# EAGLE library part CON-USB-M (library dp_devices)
USB Male connector
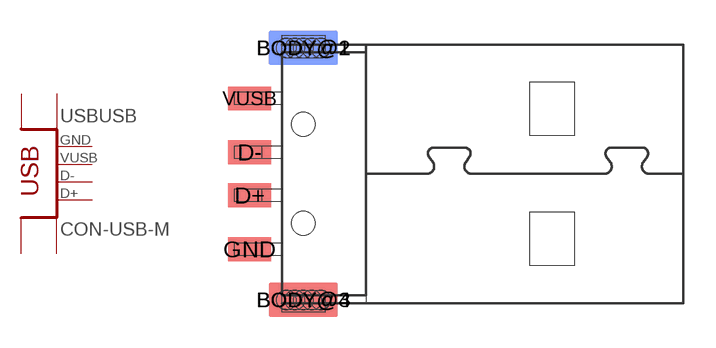
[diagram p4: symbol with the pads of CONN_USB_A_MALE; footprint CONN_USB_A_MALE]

Designator prefix USB; gates USB=CONN_USB_4P BODY=USB_BODY_PINS2

## CON-USB-M-A  [CONN_USB_A_MALE]
BODY@1  BODY:BODY  hiz
BODY@2  BODY:BODY  hiz
BODY@3  BODY:BODY  hiz
BODY@4  BODY:BODY  hiz
D+  USB:D+
D-  USB:D-
GND  USB:GND
VUSB  USB:VUSB

## Footprint CONN_USB_A_MALE (pad centres in mm)
SMD mount USB Type A Male
smd 3.2 x 1.6: BODY@1 0,5.85; BODY@3 0,-5.85
smd 3.2 x 1.6 bottom: BODY@2 0,5.85; BODY@4 0,-5.85
smd 1.99 x 1.1: D+ -2.5,-1; D- -2.5,1; GND -2.5,-3.5; VUSB -2.5,3.5
hole 1.1 at 0,2.3
hole 1.1 at 0,-2.3
hole 0.9 at -0.8,5.85
hole 0.9 at -0.4,5.85
hole 0.9 at 0,5.85
hole 0.9 at 0.4,5.85
hole 0.9 at 0.8,5.85
hole 0.9 at -0.8,-5.85
hole 0.9 at -0.4,-5.85
hole 0.9 at 0,-5.85
hole 0.9 at 0.4,-5.85
hole 0.9 at 0.8,-5.85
